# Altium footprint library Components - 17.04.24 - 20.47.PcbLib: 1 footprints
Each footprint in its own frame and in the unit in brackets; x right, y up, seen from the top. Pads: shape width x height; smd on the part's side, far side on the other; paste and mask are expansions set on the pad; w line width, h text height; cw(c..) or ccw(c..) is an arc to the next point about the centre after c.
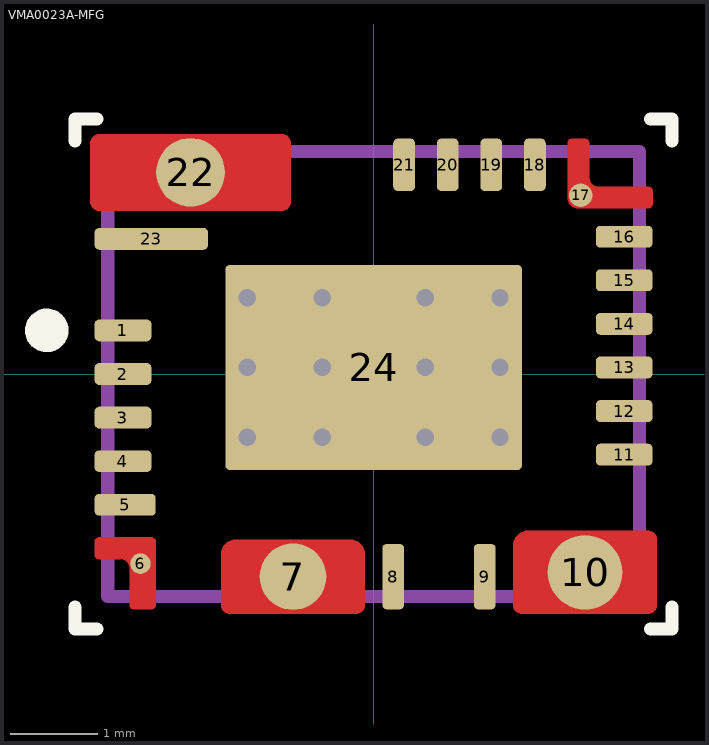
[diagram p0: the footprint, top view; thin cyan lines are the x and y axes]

## VMA0023A-MFG [mm]
pads (24):
  rrect40% 0.65x0.25 smd paste+0 mask+0: 1(-2.875,0.5) 2(-2.875,0) 3(-2.875,-0.5) 4(-2.875,-1) 11(2.875,-0.925) 12(2.875,-0.425) 13(2.875,0.075) 14(2.875,0.575) 15(2.875,1.075) 16(2.875,1.575)
  rrect40% 0.7x0.25 smd paste+0 mask+0: 5(-2.85,-1.5)
  round 0.235 smd paste+0 mask+0: 6(-2.675,-2.175)
  round 0.765 smd paste-1000 mask-1000: 7(-0.925,-2.325)
  rrect40% 0.25x0.75 smd paste+0 mask+0: 8(0.225,-2.325) 9(1.275,-2.325)
  round 0.855 smd paste-1000 mask-1000: 10(2.425,-2.275)
  round 0.27 smd paste+0 mask+0: 17(2.375,2.05)
  rrect40% 0.25x0.6 smd paste+0 mask+0: 18(1.85,2.4) 19(1.35,2.4) 20(0.85,2.4) 21(0.35,2.4)
  round 0.788 smd paste-1000 mask-1000: 22(-2.1,2.312)
  rrect40% 1.3x0.25 smd paste+0 mask+0: 23(-2.55,1.55)
  rrect4% 3.4x2.35 smd paste-1000 mask+0: 24(0,0.075)
via -1.45,0.875 diameter 0.5 hole 0.2
via -1.45,0.075 diameter 0.5 hole 0.2
via -1.45,-0.725 diameter 0.5 hole 0.2
via 1.45,-0.725 diameter 0.5 hole 0.2
via 1.45,0.075 diameter 0.5 hole 0.2
via 1.45,0.875 diameter 0.5 hole 0.2
via 0.59,-0.725 diameter 0.5 hole 0.2
via 0.59,0.075 diameter 0.5 hole 0.2
via 0.59,0.875 diameter 0.5 hole 0.2
via -0.59,-0.725 diameter 0.5 hole 0.2
via -0.59,0.075 diameter 0.5 hole 0.2
via -0.59,0.875 diameter 0.5 hole 0.2
Top Layer:
  region: -3.15,-2.125 -3.16,-2.125 -3.178,-2.117 -3.192,-2.103 -3.2,-2.085 -3.2,-2.075 -3.2,-1.925 -3.2,-1.915 -3.192,-1.897 -3.178,-1.883 -3.16,-1.875 -3.15,-1.875 -2.55,-1.875 -2.54,-1.875 -2.522,-1.883 -2.508,-1.897 -2.5,-1.915 -2.5,-1.925 -2.5,-2.65 -2.5,-2.66 -2.508,-2.678 -2.522,-2.692 -2.54,-2.7 -2.55,-2.7 -2.75,-2.7 -2.76,-2.7 -2.778,-2.692 -2.792,-2.678 -2.8,-2.66 -2.8,-2.65 -2.8,-2.225 -2.802,-2.205 -2.817,-2.169 -2.844,-2.142 -2.88,-2.127 -2.9,-2.125
  region: -1.65,-2.75 -1.67,-2.75 -1.707,-2.735 -1.735,-2.707 -1.75,-2.67 -1.75,-2.65 -1.75,-2.075 -1.75,-2.04 -1.723,-1.976 -1.674,-1.927 -1.61,-1.9 -1.575,-1.9 -0.275,-1.9 -0.24,-1.9 -0.176,-1.927 -0.127,-1.976 -0.1,-2.04 -0.1,-2.075 -0.1,-2.65 -0.1,-2.67 -0.115,-2.707 -0.143,-2.735 -0.18,-2.75 -0.2,-2.75
  region: 3.15,-1.8 3.17,-1.8 3.207,-1.815 3.235,-1.843 3.25,-1.88 3.25,-1.9 3.25,-2.65 3.25,-2.67 3.235,-2.707 3.207,-2.735 3.17,-2.75 3.15,-2.75 1.7,-2.75 1.68,-2.75 1.643,-2.735 1.615,-2.707 1.6,-2.67 1.6,-2.65 1.6,-1.975 1.6,-1.94 1.627,-1.876 1.676,-1.827 1.74,-1.8 1.775,-1.8
  region: 3.15,2.15 3.16,2.15 3.178,2.142 3.192,2.128 3.2,2.11 3.2,2.1 3.2,1.95 3.2,1.94 3.192,1.922 3.178,1.908 3.16,1.9 3.15,1.9 2.35,1.9 2.325,1.9 2.279,1.919 2.244,1.954 2.225,2 2.225,2.025 2.225,2.65 2.225,2.66 2.233,2.678 2.247,2.692 2.265,2.7 2.275,2.7 2.425,2.7 2.435,2.7 2.453,2.692 2.467,2.678 2.475,2.66 2.475,2.65 2.475,2.25 2.477,2.23 2.492,2.194 2.519,2.167 2.555,2.152 2.575,2.15
  region: -1.05,2.75 -1.03,2.75 -0.993,2.735 -0.965,2.707 -0.95,2.67 -0.95,2.65 -0.95,1.975 -0.95,1.955 -0.965,1.918 -0.993,1.89 -1.03,1.875 -1.05,1.875 -3.15,1.875 -3.17,1.875 -3.207,1.89 -3.235,1.918 -3.25,1.955 -3.25,1.975 -3.25,2.65 -3.25,2.67 -3.235,2.707 -3.207,2.735 -3.17,2.75 -3.15,2.75
Top Overlay:
  circle w0.25: c-3.75,0.5 r0.125
  lines w0.15: -3.425,-2.675 -3.425,-2.925 -3.175,-2.925 ; -3.425,2.675 -3.425,2.925 -3.175,2.925 ; 3.175,-2.925 3.425,-2.925 3.425,-2.675 ; 3.175,2.925 3.425,2.925 3.425,2.675
Top Paste:
  drawing of 9 lines, arcs and shapes, not listed
Top Solder:
  drawing of 3 lines, arcs and shapes, not listed
Mechanical 5:
  lines w0.15: -3.05,-2.55 3.05,-2.55 3.05,2.55 -3.05,2.55 -3.05,-2.55
  text ".Designator" at 0,0 h0.5
3D body "IC_TPS16890VMAR_LQFN-CLIP23.STEP": height 0.25, standoff 0, extent -3.35,-2.85 3.35,2.85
